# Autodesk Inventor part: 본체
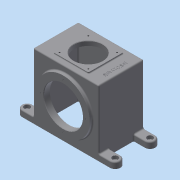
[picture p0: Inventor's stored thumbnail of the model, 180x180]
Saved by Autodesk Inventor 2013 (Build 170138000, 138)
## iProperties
Created: 2016-11
Part Number: 본체
Material: 알루미늄 6061
Document SubType Name: Modeling
Designer: mduedu
Density: 1 g/cm^3
Author: mduedu
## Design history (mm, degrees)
sketch "스케치1"
  geometry: L1 (-80, 0)-(80, 0); L2 (80, 0)-(80, 160); L3 (80, 160)-(-80, 160); L4 (-80, 160)-(-80, 0); 2 further points
  constraints: 8 end point, 2 parallel, 1 coincident, 1 horizontal, 1 midpoint, 1 perpendicular
  dimensions: "d0" = 160 distance of L2.end L3.end; "d2" = 160 distance of L1.end L2.end
extrude "돌출1" new body sketch "스케치1" stored distance "d3" = 110; taper "d4" = 0 deg
sketch "스케치2"
  geometry: L1 (-80, -55)-(-80, 55) reference; L2 (-80, -55)-(-120, -55); L3 (-120, -55)-(-120, 55); L4 (-120, 55)-(-80, 55); L5 (-80, 55)-(-80, -55); 1 further point
  constraints: 8 end point, 2 parallel, 1 horizontal, 1 perpendicular
  dimensions: "d5" = 40 distance of L1.end L3.end
extrude "돌출2" join sketch "스케치2" distance "d6" = 15; taper "d7" = 0 deg
sketch "스케치3"
  geometry: L1 (80, 55)-(80, -55) reference; L2 (120, -55)-(120, 55) reference; L3 (80, 30)-(120, 30); L4 (120, 30)-(120, -30); L5 (120, -30)-(80, -30); L6 (80, -30)-(80, 30); L7 (-80, -55)-(120, -55) reference; L8 (-80, 55)-(120, 55) reference; 1 further point
  constraints: 8 end point, 2 parallel, 2 point on line, 1 horizontal, 1 perpendicular
  dimensions: "d8" = 25 distance between parallel lines of L5 L7; "d9" = 25 distance between parallel lines of L3 L8 (= d8)
extrude "돌출3" cut sketch "스케치3" stored distance "d10" = 15; taper "d11" = 0 deg
fillet "모깎기1"
fillet "모깎기2"
hole "구멍1" diameter "d14" = 9; stored, may be unused: countersink angle "d18" = 90 deg, drill point angle "d20" = 118 deg; dims "d12" = 10, "d13" = 10, "d15" = 6, "d16" = 14, "d17" = 8, "d19" = 8
fillet "모깎기3" dims "d21" = 3
fillet "모깎기4" dims "d22" = 3
sketch "스케치4"
  geometry: L1 (80, 160)-(-80, 160) reference; L2 (-80, 17.196)-(-80, 160) reference; L3 (80, 17.196)-(80, 160) reference; L4 (-72, 0)-(-72, 152); L5 (-72, 152)-(72, 152); L6 (72, 152)-(72, 0); L7 (-72, 0)-(72, 0); 2 further points
  constraints: 8 end point, 1 coincident, 1 midpoint, 1 perpendicular
  dimensions: "d23" = 8 distance between parallel lines of L5 L1; "d24" = 8 distance between parallel lines of L3 L6 (= d23); "d25" = 8 distance between parallel lines of L2 L4 (= d23)
extrude "돌출4" cut sketch "스케치4" stored distance "d26" = 94; taper "d27" = 0 deg
fillet "모깎기5" dims "d28" = 3
fillet "모깎기6" dims "d29" = 3
fillet "모깎기7" dims "d30" = 3
fillet "모깎기8" dims "d31" = 3
sketch "스케치5"
  geometry: C1 r 65 at (0, 80); 1 further point
  constraints: 1 centre point, 1 vertical alignment
  dimensions: "d32" = 130 diameter of C1; "d33" = 80 distance of C1.centre point (0, 0)
extrude "돌출5" join sketch "스케치5" distance "d34" = 7; taper "d35" = 0 deg
sketch "스케치6"
  geometry: C1 r 35 at (77, 51.5); 2 further points
  constraints: 1 centre point, 1 coincident, 1 vertical alignment
  dimensions: "d36" = 70 diameter of C1; "d77" = 0.5 distance of point (77, 52) point (77, 51.5)
extrude "돌출6" cut sketch "스케치6" stored distance "d37" = 7; taper "d38" = 0 deg
sketch "스케치7"
  geometry: L1 (34.5, 9)-(119.5, 9); L2 (119.5, 9)-(119.5, 94); L3 (119.5, 94)-(34.5, 94); L4 (34.5, 94)-(34.5, 9); L5 (34.5, 9)-(119.5, 94); L6 (119.5, 9)-(34.5, 94); C1 r 35 at (77, 51.5) reference; 2 further points
  constraints: 12 end point, 3 midpoint, 2 parallel, 1 coincident, 1 horizontal, 1 perpendicular
  dimensions: "d39" = 85 distance of L3.end L2.end; "d40" = 85 distance of L1.end L2.end (= d39)
extrude "돌출7" join sketch "스케치7" distance "d41" = 3; taper "d42" = 0 deg
fillet "모깎기9" dims "d43" = 3
fillet "모깎기10" dims "d44" = 2
hole "구멍2" diameter "d47" = 95; stored, may be unused: countersink angle "d51" = 90 deg, drill point angle "d53" = 118 deg; dims "d45" = 10, "d46" = 10, "d48" = 6, "d49" = 14, "d50" = 8, "d52" = 8
chamfer "모따기1" distance "d54" = 1; stored, may be unused: second distance "d55" = 2, angle "d56" = 45 deg
sketch "스케치8"
  geometry: C1 r 65 at (0, 80) reference; C2 r 31.5 at (0, 80); 1 further point
  constraints: 1 centre point, 1 coincident
  dimensions: "d57" = 63 diameter of C2
extrude "돌출8" join sketch "스케치8" distance "d58" = 14; taper "d59" = 0 deg
hole "구멍3" diameter "d62" = 30; stored, may be unused: countersink angle "d66" = 90 deg, drill point angle "d68" = 0 deg; dims "d60" = 10, "d61" = 10, "d63" = 6, "d64" = 47, "d65" = 14, "d67" = 17
fillet "모깎기11" dims "d69" = 3
fillet "모깎기12" dims "d70" = 3
fillet "모깎기13" dims "d71" = 0.5
chamfer "모따기2" distance "d72" = 1; stored, may be unused: second distance "d73" = 2, angle "d74" = 45 deg
fillet "모깎기14" dims "d75" = 3
sketch "스케치9"
  geometry: L1 (157, 0)-(157, 104) reference; L2 (77, 52)-(157, 52); 1 further point
  constraints: 2 end point, 1 midpoint, 1 point on line, 1 other
  dimensions: "d78" = 65 distance of point (142, 52) L2.start
feature "엠보싱1" sketch "스케치9" dims "d79" = 0.5, "d80" = 0
sketch "스케치10"
  geometry: 4 further points
  constraints: 4 other
hole "구멍4" sketch "스케치10" at (0, -55), (55, 0), (-55, 0), (0, 55) diameter "d81" = 3.242; stored, may be unused: countersink angle "d85" = 90 deg, drill point angle "d87" = 120 deg; dims "d82" = 6.6, "d83" = 4, "d84" = 2, "d86" = 8.6
sketch "스케치11"
  geometry: 4 further points
  constraints: 4 other
hole "구멍5" sketch "스케치11" at (42, 86.5), (112, 86.5), (112, 16.5), (42, 16.5) diameter "d88" = 3.242; stored, may be unused: countersink angle "d92" = 90 deg, drill point angle "d94" = 120 deg; dims "d89" = 6.6, "d90" = 4, "d91" = 2, "d93" = 8.6
node "솔리드1"
mirror "대칭1"
mirror "대칭2"
mirror "대칭3"
